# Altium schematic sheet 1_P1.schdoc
size 309 x 223 mm; Symbol: Sheet-Symbol_A4; Device: Sheet-Symbol_A4; @Page Name: P1; @Create Date: 2024-03-17; @Page Count: 1; @Page No: 1; @Project Name: ECE590; @Schematic Name: Schematic1; @Update Date: 2024-03-20; Company: 嘉立创EDA; Page Size: A4; Version: V1.0
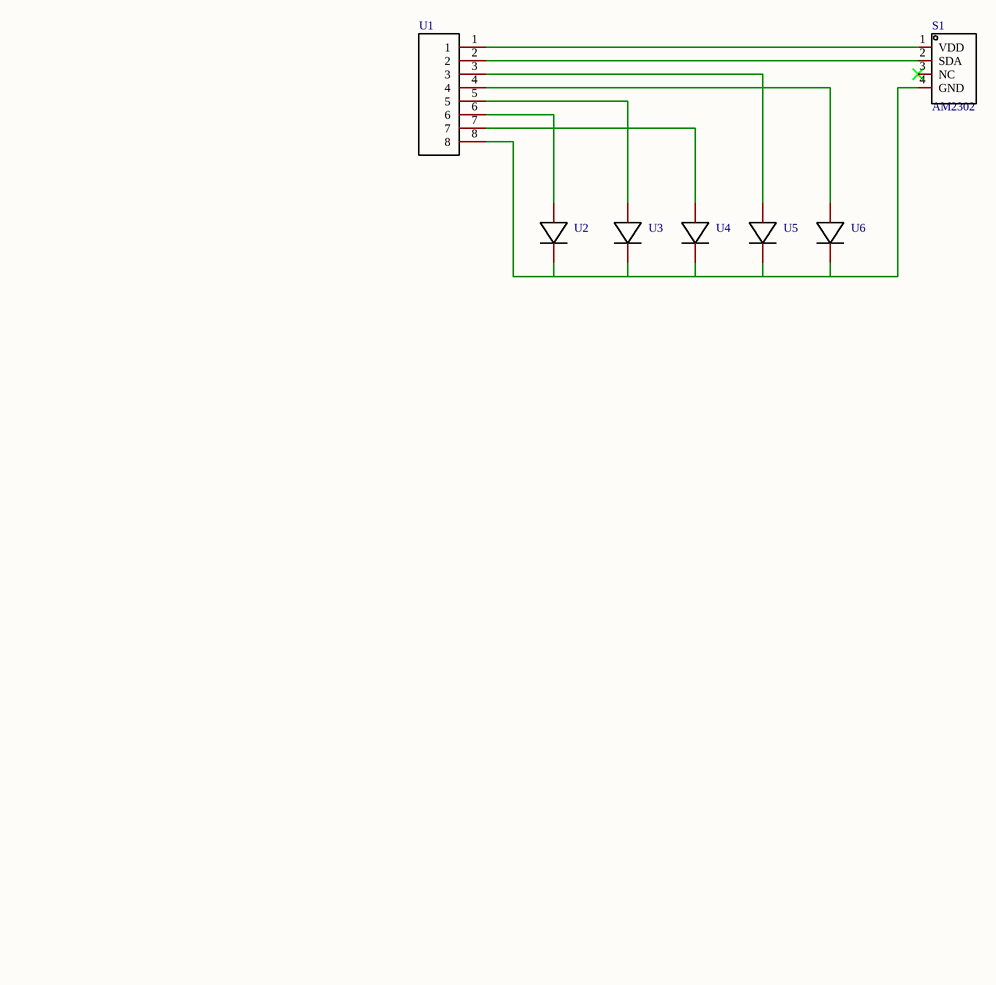
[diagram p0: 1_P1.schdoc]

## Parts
S1  AM2302  [SENSOR-TH_AM2302]
U1  PIN-8  [PIN-8]  (value not drawn)
U2  Adafruit_LED_4x9  [LED_4x9]  (value not drawn)
U3  Adafruit_LED_4x9  [LED_4x9]  (value not drawn)
U4  Adafruit_LED_4x9  [LED_4x9]  (value not drawn)
U5  Adafruit_LED_4x9  [LED_4x9]  (value not drawn)
U6  Adafruit_LED_4x9  [LED_4x9]  (value not drawn)

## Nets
NetS1_1: S1.1(VDD) U1.1
NetS1_2: S1.2(SDA) U1.2
NetS1_4: S1.4(GND) U1.8 U2.1 U3.1 U4.1 U5.1 U6.1
NetU1_3: U1.3 U5.2
NetU1_4: U1.4 U6.2
NetU1_5: U1.5 U3.2
NetU1_6: U1.6 U2.2
NetU1_7: U1.7 U4.2

Not connected (* = marked no-connect by the designer): S1 3(NC)*

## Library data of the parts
S1 = AM2302: 数字温湿度传感器25.3x15.4mmx7.8mm; Manufacturer: 广州奥松; Add into BOM: yes
U1 = PIN-8: Add into BOM: yes
U2-U6 = Adafruit_LED_4x9: Add into BOM: yes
